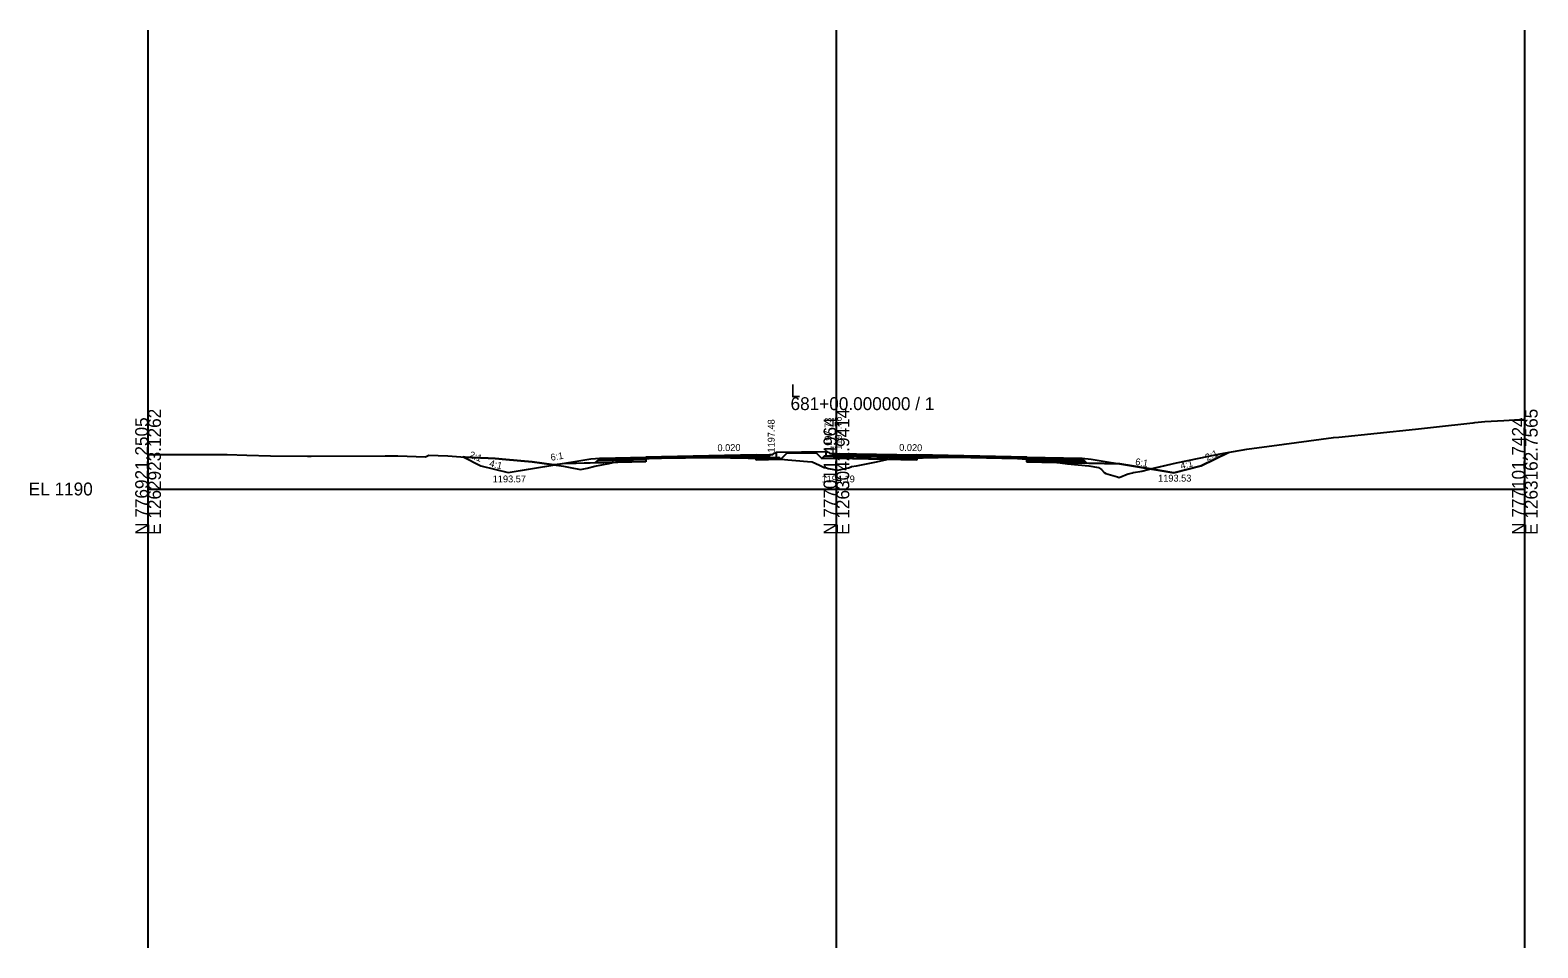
# Model space of a CAD drawing. Extents: x -41 to 1262860, y -100 to 777489.
# Drawn here: x 474.3 to 802.8, y 3625 to 3825 of the extents above; entities that cross this region are included whole.
import ezdxf

# ---------------------------------------------------------------- set-up
doc = ezdxf.new("R2010")
doc.units = 0
for name, color, linetype in [('Exist Cross Section Cell', 7, 'Continuous'), ('Exist XS Center Line Elevation Label', 7, 'Continuous'), ('Exist XS Ground Line', 7, 'Continuous'), ('Prop CMT Pvmt Course 1', 7, 'Continuous'), ('Prop CMT Pvmt Surface', 7, 'Continuous'), ('Prop CMT Shld Paved Course 1', 7, 'Continuous'), ('Prop CMT Shld Paved Course 2', 7, 'Continuous'), ('Prop CMT Shld Paved Course 4', 7, 'Continuous'), ('Prop CMT Subgrade Earthwork', 7, 'Continuous'), ('Prop Conc Curb and Gutter', 7, 'Continuous'), ('Prop Conc Island Cover', 7, 'Continuous'), ('Prop XS Ditch Standard Text', 7, 'Continuous'), ('Prop XS Earthwork Shape', 7, 'Continuous'), ('Prop XS Elevation Labels', 7, 'Continuous'), ('Prop XS Exc Vertical Line 1', 7, 'Continuous'), ('Prop XS Exc Vertical Line 2', 7, 'Continuous'), ('Prop XS Exc Vertical Line 3', 7, 'Continuous'), ('Prop XS Finish Grade', 7, 'Continuous'), ('Prop XS Hydro Elevations', 7, 'Continuous'), ('Prop XS SE Text', 7, 'Continuous'), ('Prop XS Side Slope Text', 7, 'Continuous'), ('Scratch_Level_4', 7, 'Continuous'), ('Scratch_Level_6', 7, 'Continuous')]:
    doc.layers.add(name, color=color, linetype=linetype)

msp = doc.modelspace()

# ---------------------------------------------------------------- linework, layer by layer
at = {"layer": 'Exist Cross Section Cell'}
for p, q in [((650, 3725), (650, 3745)), ((500, 3725), (650, 3725)), ((650, 3725), (800, 3725))]:
    msp.add_line(p, q, dxfattribs=at)
at = {"layer": 'Exist XS Ground Line'}
msp.add_lwpolyline([(500, 3732.51), (508.58, 3732.5), (511.86, 3732.49), (517.23, 3732.49), (521.49, 3732.37), (526.71, 3732.22), (534.77, 3732.15), (535.07, 3732.14), (535.18, 3732.15), (535.53, 3732.15), (551.65, 3732.25), (553.55, 3732.21), (554.44, 3732.21), (560.49, 3732.03), (561, 3732.28), (561.14, 3732.36), (565.3, 3732.22), (569.07, 3731.96), (574.08, 3731.74), (575.65, 3731.65), (577.94, 3731.44), (583.69, 3730.95), (587.88, 3730.37), (590.5, 3729.97), (592.01, 3729.7), (594.23, 3729.24), (595.71, 3729.56), (597.35, 3729.94), (600.4, 3730.59), (602.69, 3731.07), (604.2, 3731.18), (607.36, 3731.52), (609.22, 3731.65), (610.67, 3731.75), (617.09, 3731.82), (622.99, 3731.9), (634.72, 3731.67), (635.44, 3731.66), (635.65, 3731.64), (637.28, 3731.54), (639.44, 3731.37), (641.13, 3731.22), (643.72, 3731.01), (644.69, 3730.92), (646.28, 3730.21), (647.31, 3729.72), (647.86, 3729.59), (648.21, 3729.49), (650.32, 3729.13), (652.28, 3729.51), (652.66, 3729.61), (653.22, 3729.86), (653.23, 3729.79), (653.25, 3729.87), (654.34, 3730.07), (658.73, 3730.94), (661.56, 3731.54), (664.84, 3731.71), (665.39, 3731.74), (675.42, 3731.91), (677.39, 3731.94), (679.32, 3731.89), (689.48, 3731.66), (692.79, 3731.43), (693.42, 3731.39), (698.77, 3730.68), (700.38, 3730.49), (704.97, 3730.03), (707.09, 3729.7), (707.76, 3729.27), (708.35, 3728.61), (708.73, 3728.35), (711.23, 3727.64), (711.57, 3727.54), (711.96, 3727.65), (713.36, 3728.21), (713.55, 3728.34), (714.59, 3728.55), (714.67, 3728.58), (714.72, 3728.59), (716.56, 3728.88), (718.25, 3729.33), (724.09, 3730.73), (733.61, 3732.68), (739.44, 3733.67), (747.54, 3734.8), (758.3, 3736.2), (759.47, 3736.33), (776.15, 3738.01), (780.74, 3738.55), (788.02, 3739.36), (788.76, 3739.44), (789.11, 3739.48), (791.26, 3739.72), (795.43, 3739.94), (800, 3740.19)], dxfattribs=at)
at = {"layer": 'Prop CMT Pvmt Course 1'}
for p, q in [((632.5, 3732.16), (635.41, 3732.22)), ((635.41, 3732.47), (635.41, 3732.22)), ((649.29, 3732.75), (649.29, 3732.5))]:
    msp.add_line(p, q, dxfattribs=at)
for points in [[(608.5, 3731.93), (608.5, 3731.68), (632.5, 3732.16), (632.5, 3732.16), (632.5, 3732.41), (632.5, 3732.41), (632.5, 3732.41), (608.5, 3731.93), (608.5, 3731.93)], [(649.29, 3732.5), (650, 3732.51), (667.49, 3732.16)], [(691.5, 3731.93), (691.5, 3731.93), (667.5, 3732.41), (667.5, 3732.41), (667.5, 3732.41), (667.5, 3732.16), (667.5, 3732.16), (691.5, 3731.68), (691.5, 3731.93)]]:
    msp.add_lwpolyline(points, dxfattribs=at)
at = {"layer": 'Prop CMT Pvmt Surface'}
for p, q in [((608.5, 3731.93), (632.5, 3732.41)), ((632.5, 3732.41), (635.41, 3732.47)), ((667.5, 3732.41), (691.5, 3731.93)), ((598.5, 3731.73), (608.5, 3731.93)), ((691.5, 3731.93), (703.5, 3731.69))]:
    msp.add_line(p, q, dxfattribs=at)
msp.add_lwpolyline([(649.29, 3732.75), (650, 3732.76), (667.5, 3732.41)], dxfattribs=at)
at = {"layer": 'Prop CMT Shld Paved Course 1'}
for p, q in [((598.24, 3731.48), (598.5, 3731.73)), ((608.5, 3731.68), (598.24, 3731.48)), ((604.5, 3731.85), (604.5, 3731.85)), ((608.5, 3731.93), (608.5, 3731.93)), ((608.5, 3731.93), (608.5, 3731.93)), ((608.5, 3731.93), (608.5, 3731.68)), ((608.5, 3731.68), (608.5, 3731.68)), ((691.5, 3731.93), (691.5, 3731.93)), ((691.5, 3731.93), (691.5, 3731.93)), ((691.5, 3731.93), (691.5, 3731.68)), ((691.5, 3731.68), (691.5, 3731.68)), ((691.5, 3731.68), (703.76, 3731.44)), ((695.5, 3731.85), (695.5, 3731.85)), ((703.76, 3731.44), (703.5, 3731.69))]:
    msp.add_line(p, q, dxfattribs=at)
at = {"layer": 'Prop CMT Shld Paved Course 2'}
for p, q in [((622.99, 3731.97), (632.5, 3732.16)), ((632.5, 3732.16), (632.5, 3732.16)), ((632.5, 3732.16), (632.5, 3732.16)), ((632.5, 3732.16), (632.5, 3731.83)), ((635.41, 3731.89), (635.41, 3732.22)), ((649.29, 3732.16), (649.29, 3732.5)), ((675.42, 3732), (667.5, 3732.16)), ((667.5, 3732.16), (667.5, 3732.16)), ((667.5, 3732.16), (667.5, 3732.16)), ((667.5, 3732.16), (667.5, 3731.83)), ((597.9, 3731.14), (598.24, 3731.48)), ((608.5, 3731.35), (597.9, 3731.14)), ((604.24, 3731.6), (604.24, 3731.6)), ((608.5, 3731.68), (609.22, 3731.7)), ((608.5, 3731.68), (608.5, 3731.68)), ((608.5, 3731.68), (608.5, 3731.68)), ((608.5, 3731.68), (608.5, 3731.35)), ((608.5, 3731.6), (608.5, 3731.68)), ((608.5, 3731.68), (608.5, 3731.68)), ((609.22, 3731.65), (608.5, 3731.6)), ((608.5, 3731.35), (608.5, 3731.35)), ((609.22, 3731.7), (610.67, 3731.73)), ((610.18, 3731.72), (609.22, 3731.65)), ((609.22, 3731.7), (609.22, 3731.7)), ((609.22, 3731.65), (609.22, 3731.65)), ((610.67, 3731.73), (610.18, 3731.72)), ((610.18, 3731.72), (610.18, 3731.72)), ((610.67, 3731.73), (617.09, 3731.85)), ((613.14, 3731.77), (610.67, 3731.73)), ((617.09, 3731.82), (613.14, 3731.77)), ((613.14, 3731.77), (613.14, 3731.77)), ((617.09, 3731.85), (622.99, 3731.97)), ((622.99, 3731.9), (617.09, 3731.82)), ((617.09, 3731.85), (617.09, 3731.85)), ((617.09, 3731.82), (617.09, 3731.82)), ((622.99, 3731.97), (622.99, 3731.97)), ((622.99, 3731.97), (622.99, 3731.97)), ((629.63, 3731.77), (622.99, 3731.9)), ((622.99, 3731.9), (622.99, 3731.9)), ((622.99, 3731.9), (622.99, 3731.9)), ((632.5, 3731.83), (629.63, 3731.77)), ((629.63, 3731.77), (629.63, 3731.77)), ((632.5, 3731.83), (635.41, 3731.89)), ((632.5, 3731.83), (632.5, 3731.83)), ((667.5, 3731.83), (667.5, 3731.83)), ((667.5, 3731.83), (667.5, 3731.83)), ((667.5, 3731.83), (668.99, 3731.8)), ((668.99, 3731.8), (675.42, 3731.91)), ((677.39, 3731.96), (675.42, 3732)), ((675.42, 3732), (675.42, 3732)), ((675.42, 3731.91), (677.39, 3731.94)), ((675.42, 3731.91), (675.42, 3731.91)), ((679.32, 3731.93), (677.39, 3731.96)), ((677.39, 3731.94), (679.32, 3731.89)), ((689.48, 3731.72), (679.32, 3731.93)), ((679.32, 3731.93), (679.32, 3731.93)), ((679.32, 3731.89), (679.32, 3731.89)), ((679.32, 3731.89), (689.48, 3731.66)), ((691.5, 3731.68), (689.48, 3731.72)), ((689.48, 3731.72), (689.48, 3731.72)), ((689.48, 3731.72), (689.48, 3731.72)), ((689.48, 3731.66), (689.48, 3731.66)), ((689.48, 3731.66), (689.48, 3731.66)), ((689.48, 3731.66), (691.5, 3731.52)), ((691.5, 3731.68), (691.5, 3731.68)), ((691.5, 3731.68), (691.5, 3731.68)), ((691.5, 3731.68), (691.5, 3731.35)), ((691.5, 3731.52), (691.5, 3731.68)), ((691.5, 3731.68), (691.5, 3731.68)), ((691.5, 3731.68), (691.5, 3731.68)), ((691.5, 3731.52), (691.5, 3731.52)), ((691.5, 3731.35), (691.5, 3731.35)), ((691.5, 3731.35), (704.1, 3731.1)), ((704.1, 3731.1), (703.76, 3731.44))]:
    msp.add_line(p, q, dxfattribs=at)
msp.add_lwpolyline([(649.29, 3732.16), (650, 3732.18), (667.5, 3731.83)], dxfattribs=at)
at = {"layer": 'Prop CMT Shld Paved Course 4'}
for p, q in [((649.29, 3732.16), (647.29, 3732.12)), ((597.44, 3730.67), (597.9, 3731.14)), ((608.5, 3730.89), (597.44, 3730.67)), ((603.4, 3731.25), (603.4, 3731.25)), ((603.9, 3731.26), (603.9, 3731.26)), ((608.5, 3731.35), (608.5, 3731.35)), ((608.5, 3731.35), (608.5, 3731.35)), ((608.5, 3731.35), (608.5, 3730.89)), ((629.63, 3731.77), (632.5, 3731.72)), ((632.5, 3731.83), (637.41, 3731.93)), ((632.5, 3731.83), (632.5, 3731.37)), ((632.5, 3731.37), (637.86, 3731.48)), ((637.41, 3731.93), (637.86, 3731.48)), ((647.29, 3732.12), (646.83, 3731.66)), ((649.29, 3731.71), (646.83, 3731.66)), ((667.5, 3731.83), (667.5, 3731.37)), ((668.99, 3731.8), (667.5, 3731.77)), ((691.5, 3731.35), (691.5, 3731.35)), ((691.5, 3731.35), (691.5, 3731.35)), ((691.5, 3731.35), (691.5, 3730.89)), ((691.5, 3730.89), (704.56, 3730.63)), ((704.56, 3730.63), (704.1, 3731.1))]:
    msp.add_line(p, q, dxfattribs=at)
msp.add_lwpolyline([(649.29, 3731.71), (650, 3731.72), (667.5, 3731.37)], dxfattribs=at)
at = {"layer": 'Prop CMT Subgrade Earthwork'}
for p, q in [((637.86, 3731.48), (639.35, 3732.96)), ((646.83, 3731.66), (645.4, 3733.08)), ((608.5, 3730.89), (590.22, 3730.52)), ((608.5, 3731.6), (608.5, 3730.89)), ((632.5, 3731.72), (632.5, 3731.37)), ((637.86, 3731.48), (632.5, 3731.37)), ((646.83, 3731.66), (650, 3731.72)), ((650, 3731.72), (667.5, 3731.37)), ((667.5, 3731.37), (667.5, 3731.77)), ((691.5, 3731.52), (691.5, 3730.89)), ((691.5, 3730.89), (711.78, 3730.48))]:
    msp.add_line(p, q, dxfattribs=at)
at = {"layer": 'Prop Conc Curb and Gutter'}
for p, q in [((636.1, 3732.48), (635.41, 3732.47)), ((635.41, 3731.89), (635.41, 3732.47)), ((636.16, 3732.56), (636.16, 3732.55)), ((636.91, 3732.92), (636.26, 3732.7)), ((636.91, 3731.92), (636.91, 3732.92)), ((647.79, 3733.13), (648.44, 3732.94)), ((647.79, 3732.13), (647.79, 3733.13)), ((649.29, 3732.16), (647.79, 3732.13)), ((648.54, 3732.81), (648.54, 3732.79)), ((648.61, 3732.73), (649.29, 3732.75)), ((649.29, 3732.16), (649.29, 3732.75)), ((635.41, 3731.89), (636.91, 3731.92))]:
    msp.add_line(p, q, dxfattribs=at)
for centre, radius, start, end in [((636.1, 3732.55), 0.0625, 271.1458, 360), ((636.31, 3732.56), 0.146, 108.435, 180), ((648.4, 3732.8), 0.146, 2.2915, 73.8566), ((648.6, 3732.8), 0.0625, 182.2915, 271.1458)]:
    msp.add_arc(centre, radius, start, end, dxfattribs=at)
at = {"layer": 'Prop Conc Island Cover'}
msp.add_line((647.79, 3733.13), (636.91, 3732.92), dxfattribs=at)
at = {"layer": 'Prop XS Earthwork Shape'}
for points in [[(658.73, 3730.94), (661.33, 3731.49), (650, 3731.72), (646.83, 3731.66), (645.65, 3732.84), (639.09, 3732.71), (637.88, 3731.5), (639.44, 3731.37), (641.13, 3731.22), (643.72, 3731.01), (644.69, 3730.92), (646.28, 3730.21), (647.31, 3729.72), (647.86, 3729.59), (648.21, 3729.49), (650.32, 3729.13), (652.28, 3729.51), (652.66, 3729.61), (653.22, 3729.86), (653.23, 3729.79), (653.25, 3729.87), (654.34, 3730.07)], [(724.09, 3730.73), (733.61, 3732.68), (735.41, 3732.99), (729.5, 3730.03), (723.5, 3728.53), (718.44, 3729.37)], [(578.5, 3728.57), (588.61, 3730.26), (587.88, 3730.37), (583.69, 3730.95), (577.94, 3731.44), (575.65, 3731.65), (574.08, 3731.74), (569.07, 3731.96), (568.66, 3731.99), (572.5, 3730.07)], [(588.61, 3730.26), (590.5, 3729.97), (592.01, 3729.7), (594.23, 3729.24), (595.71, 3729.56), (597.35, 3729.94), (600.4, 3730.59), (601.12, 3730.74), (597.44, 3730.67), (590.22, 3730.52)], [(608.5, 3730.89), (601.12, 3730.74), (602.69, 3731.07), (604.2, 3731.18), (607.36, 3731.52), (608.5, 3731.6)], [(634.72, 3731.67), (635.44, 3731.66), (635.65, 3731.64), (637.28, 3731.54), (637.88, 3731.5), (637.86, 3731.48), (632.5, 3731.37), (632.5, 3731.72)], [(661.33, 3731.49), (661.56, 3731.54), (664.84, 3731.71), (665.39, 3731.74), (667.5, 3731.77), (667.5, 3731.37)], [(691.5, 3731.52), (692.79, 3731.43), (693.42, 3731.39), (698.18, 3730.76), (691.5, 3730.89)], [(713.36, 3728.21), (713.55, 3728.34), (714.59, 3728.55), (714.67, 3728.58), (714.72, 3728.59), (716.56, 3728.88), (718.25, 3729.33), (718.44, 3729.37), (711.78, 3730.48), (704.56, 3730.63), (698.18, 3730.76), (698.77, 3730.68), (700.38, 3730.49), (704.97, 3730.03), (707.09, 3729.7), (707.76, 3729.27), (708.35, 3728.61), (708.73, 3728.35), (711.23, 3727.64), (711.57, 3727.54), (711.96, 3727.65)]]:
    msp.add_lwpolyline(points, close=True, dxfattribs=at)
at = {"layer": 'Prop XS Exc Vertical Line 1'}
msp.add_line((500, 3625), (500, 3825), dxfattribs=at)
at = {"layer": 'Prop XS Exc Vertical Line 2'}
msp.add_line((650, 3625), (650, 3825), dxfattribs=at)
at = {"layer": 'Prop XS Exc Vertical Line 3'}
msp.add_line((800, 3625), (800, 3825), dxfattribs=at)
at = {"layer": 'Prop XS Finish Grade'}
for p, q in [((729.5, 3730.03), (735.41, 3732.99)), ((568.66, 3731.99), (572.5, 3730.07)), ((572.5, 3730.07), (578.5, 3728.57)), ((578.5, 3728.57), (596.5, 3731.57)), ((596.5, 3731.57), (598.5, 3731.73)), ((598.5, 3731.73), (597.44, 3730.67)), ((703.5, 3731.69), (705.5, 3731.53)), ((703.5, 3731.69), (704.56, 3730.63)), ((705.5, 3731.53), (723.5, 3728.53)), ((723.5, 3728.53), (729.5, 3730.03))]:
    msp.add_line(p, q, dxfattribs=at)
at = {"layer": 'Scratch_Level_4'}
msp.add_line((800, 3625), (800, 3825), dxfattribs=at)
at = {"layer": 'Scratch_Level_6'}
msp.add_line((500, 3625), (500, 3825), dxfattribs=at)

# ---------------------------------------------------------------- texts
at = {"layer": 'Exist Cross Section Cell'}
for s, p in [('L', (640, 3745)), ('681+00.000000 / 1', (640, 3742.2)), ('EL 1190', (474, 3723.6))]:
    msp.add_text(s, height=2.8, dxfattribs=at).set_placement(p)
for s, p in [('E 1262923.1262', (502.8, 3715)), ('E 1263042.9414', (652.8, 3715)), ('E 1263162.7565', (802.8, 3715)), ('N 776921.2505', (500, 3715)), ('N 777011.4964', (650, 3715)), ('N 777101.7424', (800, 3715))]:
    msp.add_text(s, height=2.8, rotation=90, dxfattribs=at).set_placement(p)
at = {"layer": 'Exist XS Center Line Elevation Label'}
msp.add_text('1194.19', height=1.5, dxfattribs=at).set_placement((646.75, 3726.44))
at = {"layer": 'Prop XS Ditch Standard Text'}
for s, p in [('1193.57', (575.1, 3726.44)), ('1193.53', (720.09, 3726.61))]:
    msp.add_text(s, height=1.5, dxfattribs=at).set_placement(p)
at = {"layer": 'Prop XS Elevation Labels'}
for s, p in [('1197.48', (636.54, 3732.94)), ('1197.73', (648.93, 3733.29))]:
    msp.add_text(s, height=1.5, rotation=90, dxfattribs=at).set_placement(p)
at = {"layer": 'Prop XS Hydro Elevations'}
msp.add_text('1197.76', height=1.5, rotation=90, dxfattribs=at).set_placement((651.15, 3733.55))
at = {"layer": 'Prop XS SE Text'}
for rotation, p in [(1.1458, (624.09, 3733.22)), (358.8542, (663.66, 3733.33))]:
    msp.add_text('0.020', height=1.5, rotation=rotation, dxfattribs=at).set_placement(p)
at = {"layer": 'Prop XS Side Slope Text'}
for s, rotation, p in [('2:1', 338.2726, (569.82, 3731.92)), ('6:1', 9.4623, (587.83, 3731.13)), ('2:1', 24.7387, (730.78, 3731.09)), ('4:1', 345.9638, (574.25, 3729.95)), ('6:1', 350.5377, (715.03, 3730.27)), ('4:1', 14.0362, (725.13, 3729.29))]:
    msp.add_text(s, height=1.5, rotation=rotation, dxfattribs=at).set_placement(p)

doc.saveas('drawing.dxf')
